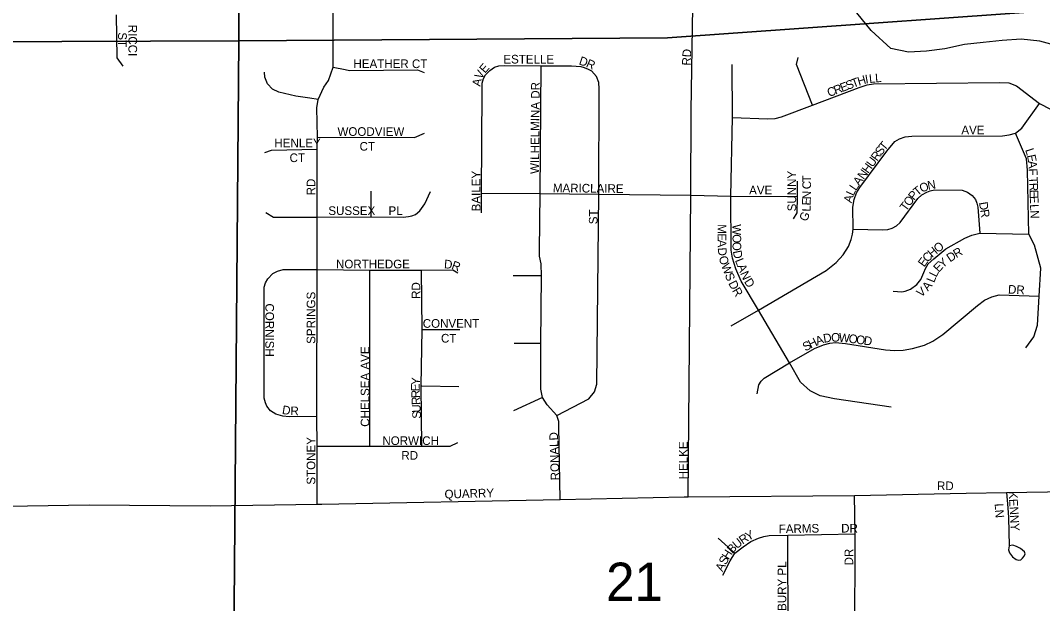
# Model space of a CAD drawing. Extents: x 8.5 to 81.5, y -1.2 to 22.4.
# Drawn here: x 50.981 to 52.1, y 18.242 to 18.88 of the extents above; entities that cross this region are included whole.
import ezdxf

# ---------------------------------------------------------------- set-up
doc = ezdxf.new("R2010")
doc.units = 0
for name, color, linetype in [('GM_X_City_Street', 7, 'Continuous'), ('GM_X_City_Street_Text', 7, 'Continuous'), ('GM_X_Minor_River', 7, 'Continuous'), ('GM_X_Section', 7, 'Continuous'), ('GM_X_Section_Text', 7, 'Continuous')]:
    doc.layers.add(name, color=color, linetype=linetype)

msp = doc.modelspace()

# ---------------------------------------------------------------- linework, layer by layer
at = {"layer": 'GM_X_City_Street'}
for points in [[(51.7122, 18.359), (51.715, 18.6889), (51.7156, 18.7812), (51.7174, 18.8951), (51.7191, 18.9313), (51.7226, 19.0378), (51.7258, 19.1233)], [(51.3058, 18.3509), (51.3059, 18.4145), (51.3056, 18.4467), (51.3059, 18.6075), (51.3058, 18.6651), (51.3059, 18.7393), (51.3062, 18.7524), (51.3056, 18.7847), (51.3071, 18.7938), (51.3132, 18.8072), (51.3182, 18.8144), (51.3234, 18.8291), (51.3232, 18.8883)], [(51.0858, 18.8862), (51.0865, 18.8393), (51.0929, 18.8302)], [(51.8486, 18.7875), (51.831, 18.832), (51.8326, 18.8398)], [(51.3071, 18.7938), (51.2978, 18.795), (51.2823, 18.7974), (51.2638, 18.8018), (51.2569, 18.805), (51.2514, 18.8109), (51.2485, 18.8182), (51.2482, 18.8235)], [(51.3234, 18.8291), (51.3364, 18.8264), (51.3414, 18.8254), (51.4157, 18.8262), (51.4231, 18.8232)], [(51.4857, 18.6698), (51.4857, 18.6912), (51.4865, 18.8033), (51.4865, 18.8116), (51.4881, 18.8166), (51.4904, 18.8207), (51.4948, 18.8255), (51.5, 18.8291)], [(51.5, 18.8291), (51.505, 18.8306), (51.5107, 18.831), (51.5513, 18.8307), (51.5846, 18.8306), (51.5947, 18.8299), (51.5983, 18.8288), (51.6026, 18.827), (51.6063, 18.825)], [(51.5683, 18.448), (51.5577, 18.4597), (51.5528, 18.4675), (51.5508, 18.4767), (51.5509, 18.5265), (51.5517, 18.6008), (51.5513, 18.6138), (51.5493, 18.6223), (51.5493, 18.6286), (51.55, 18.691), (51.5513, 18.8307)], [(51.5721, 18.3561), (51.5705, 18.436), (51.5705, 18.4413), (51.5683, 18.448), (51.6035, 18.4661), (51.6098, 18.4739), (51.6122, 18.4823), (51.6144, 18.6901), (51.6149, 18.8055), (51.6145, 18.8123), (51.6118, 18.8189), (51.6063, 18.825)], [(51.9346, 18.4569), (51.8726, 18.4663), (51.857, 18.4695), (51.8458, 18.4749), (51.8354, 18.4843), (51.8233, 18.5054), (51.7893, 18.5632), (51.7703, 18.5948), (51.7645, 18.6085), (51.7607, 18.6199), (51.7593, 18.6289), (51.7591, 18.6881), (51.7609, 18.7739), (51.7606, 18.8319)], [(51.7609, 18.7739), (51.799, 18.7725), (51.8074, 18.773), (51.8146, 18.7746), (51.8486, 18.7875), (51.8997, 18.8069), (51.9083, 18.8096), (51.9153, 18.8107), (52.0531, 18.8123), (52.0634, 18.8118), (52.072, 18.8085), (52.0969, 18.7893), (52.1092, 18.7833), (52.1164, 18.7805), (52.1264, 18.779), (52.1424, 18.7778), (52.2174, 18.7786)], [(51.7595, 18.5461), (51.7893, 18.5632), (51.8634, 18.6067), (51.8742, 18.6152), (51.8819, 18.6237), (51.8877, 18.6327), (51.8908, 18.6406), (51.8923, 18.6462), (51.8931, 18.6518), (51.8927, 18.6757), (51.8939, 18.6841), (51.8968, 18.6915), (51.9003, 18.6974), (51.9299, 18.7371), (51.9387, 18.7479), (51.9437, 18.7507), (51.9499, 18.753), (51.9573, 18.7535), (52.0565, 18.754), (52.0639, 18.7551), (52.0707, 18.7569), (52.0776, 18.7624), (52.0969, 18.7893)], [(51.3062, 18.7524), (51.4125, 18.7522), (51.4235, 18.7569)], [(52.0822, 18.5221), (52.091, 18.5341), (52.0948, 18.5467), (52.0968, 18.5783), (52.0986, 18.6091), (52.0917, 18.6343), (52.0854, 18.6463), (52.0841, 18.7162), (52.0828, 18.7288), (52.0707, 18.7569)], [(51.2486, 18.7356), (51.2557, 18.7384), (51.3059, 18.7393)], [(51.8276, 18.6632), (51.8315, 18.6698), (51.8319, 18.6876), (51.8321, 18.7044)], [(51.3058, 18.6651), (51.3651, 18.6653), (51.4, 18.6651), (51.4059, 18.6656), (51.4095, 18.6663), (51.4135, 18.6679), (51.4182, 18.6719), (51.4236, 18.6795), (51.43, 18.6929)], [(51.3651, 18.6653), (51.365, 18.6934)], [(51.4857, 18.6912), (51.55, 18.691), (51.6144, 18.6901), (51.715, 18.6889), (51.7591, 18.6881), (51.8319, 18.6876)], [(51.8931, 18.6518), (51.925, 18.651), (51.9309, 18.6515), (51.9358, 18.6529), (51.9405, 18.6553), (51.9444, 18.6591), (51.9639, 18.6855), (51.9681, 18.6895), (51.9736, 18.6924), (51.9773, 18.6939), (51.982, 18.6948), (52.0124, 18.6945), (52.0181, 18.6924), (52.0233, 18.6887), (52.0269, 18.6842), (52.0285, 18.6801), (52.0296, 18.676), (52.0319, 18.6473)], [(51.2496, 18.6699), (51.2581, 18.665), (51.3058, 18.6651)], [(51.9368, 18.5838), (51.9463, 18.5834), (51.9498, 18.584), (51.9557, 18.5863), (51.9626, 18.5912), (51.967, 18.5966), (51.9704, 18.6042), (51.9721, 18.6088), (51.9752, 18.6137), (51.9813, 18.6195), (51.9946, 18.6302), (52.0154, 18.6418), (52.0231, 18.6454), (52.0319, 18.6473), (52.0854, 18.6463)], [(51.3056, 18.4467), (51.275, 18.4464), (51.2681, 18.447), (51.2605, 18.4494), (51.2546, 18.4531), (51.2508, 18.458), (51.2491, 18.4618), (51.2479, 18.4667), (51.2477, 18.4714), (51.2477, 18.5883), (51.2493, 18.5932), (51.2518, 18.5974), (51.2573, 18.6033), (51.2624, 18.606), (51.2686, 18.6075)], [(51.2686, 18.6075), (51.3059, 18.6075), (51.3635, 18.607), (51.42, 18.6068), (51.4543, 18.6072), (51.4601, 18.6041)], [(51.3637, 18.4142), (51.3635, 18.607)], [(51.4206, 18.4142), (51.4198, 18.4805), (51.4208, 18.5421), (51.42, 18.6068)], [(51.5517, 18.6008), (51.5204, 18.6009)], [(51.7879, 18.4715), (51.7898, 18.4814), (51.7921, 18.4853), (51.7956, 18.4887), (51.8233, 18.5054), (51.8505, 18.5211), (51.8604, 18.5253), (51.8673, 18.5272), (51.8737, 18.5276), (51.8845, 18.5265), (51.9283, 18.5196), (51.9386, 18.5189), (51.9478, 18.5195), (51.958, 18.5211), (51.9712, 18.525), (51.9801, 18.5291), (51.9913, 18.5364), (52.029, 18.5681), (52.0367, 18.5741), (52.045, 18.5779), (52.053, 18.5798), (52.0968, 18.5783)], [(51.4208, 18.5421), (51.462, 18.5421)], [(51.5509, 18.5265), (51.5218, 18.5265)], [(51.4198, 18.4805), (51.4206, 18.4805), (51.461, 18.4797)], [(51.5528, 18.4675), (51.5208, 18.453)], [(51.3059, 18.4145), (51.3637, 18.4142), (51.4206, 18.4142), (51.4514, 18.4142), (51.46, 18.4182)], [(51.7078, 18.3589), (51.7122, 18.359), (51.8946, 18.3605), (52.0166, 18.3628), (52.0609, 18.3636), (52.1282, 18.3647), (52.2138, 18.3662)], [(52.0609, 18.3636), (52.0624, 18.3467), (52.0631, 18.3363), (52.064, 18.3054), (52.0631, 18.3009), (52.0642, 18.2975), (52.0674, 18.2932), (52.0716, 18.2903), (52.0741, 18.2896), (52.0766, 18.2901), (52.0786, 18.2917), (52.0804, 18.2941), (52.0813, 18.2966), (52.0806, 18.2988), (52.0764, 18.3022), (52.0719, 18.3047), (52.0678, 18.3058), (52.064, 18.3054)], [(50.8944, 18.3484), (50.9434, 18.3484), (51.0561, 18.3501), (51.1886, 18.349), (51.3058, 18.3509), (51.3111, 18.351)], [(51.3111, 18.351), (51.5721, 18.3561), (51.7078, 18.3589)], [(51.8743, 18.1572), (51.8844, 18.1707), (51.8897, 18.1812), (51.894, 18.1934), (51.8949, 18.2009), (51.895, 18.3183), (51.8946, 18.3605)], [(51.7502, 18.2733), (51.7581, 18.2889), (51.7635, 18.2974), (51.7723, 18.3043), (51.7807, 18.3101), (51.7892, 18.3135), (51.795, 18.3156), (51.801, 18.3164), (51.8215, 18.3169), (51.895, 18.3183)], [(51.8218, 18.2082), (51.8215, 18.3169)], [(51.7635, 18.2974), (51.745, 18.3136)]]:
    msp.add_lwpolyline(points, dxfattribs=at)
at = {"layer": 'GM_X_Minor_River'}
msp.add_lwpolyline([(52.1177, 18.8519), (52.0975, 18.8576), (52.077, 18.8598), (52.0561, 18.8583), (52.0352, 18.856), (52.015, 18.8538), (51.9933, 18.8492), (51.9732, 18.8466), (51.9534, 18.8454), (51.9344, 18.8496), (51.9127, 18.8694), (51.8971, 18.8887), (51.8842, 18.9085), (51.8785, 18.9305), (51.8758, 18.9514), (51.8682, 18.9708), (51.8541, 18.9898), (51.8401, 19.0114), (51.8279, 19.0316), (51.8085, 19.0278), (51.7948, 19.0197)], dxfattribs=at)
at = {"layer": 'GM_X_Section'}
for points in [[(51.2391, 19.8686), (51.2184, 19.3702), (51.2202, 18.8578), (50.2509, 18.8543), (50.2547, 19.342), (50.2812, 19.8687)], [(52.284, 19.8673), (52.2219, 19.2023), (52.2136, 18.8983), (51.6895, 18.8611), (51.2202, 18.8578), (51.2184, 19.3702), (51.2391, 19.8686)], [(52.2136, 18.8983), (52.2149, 17.8371), (51.2117, 17.8427), (51.2202, 18.8578), (51.6895, 18.8611)], [(50.2509, 18.8543), (51.2202, 18.8578), (51.2117, 17.8427), (50.2502, 17.8478)]]:
    msp.add_lwpolyline(points, close=True, dxfattribs=at)

# ---------------------------------------------------------------- texts
at = {"layer": 'GM_X_City_Street_Text'}
for s, rotation, p in [('ST', 270, (51.0878, 18.8672)), ('RICCI', 270, (51.0991, 18.8755)), ('RD', 86.989, (51.7148, 18.8306)), ('HEATHER CT', 0, (51.3456, 18.8281)), ('E', 49.4491, (51.4897, 18.8218)), ('ESTELLE', 0, (51.5098, 18.8331)), ('D', 341.7932, (51.5919, 18.8322)), ('R', 336.0967, (51.5996, 18.8297)), ('V', 60.678, (51.4859, 18.815)), ('I', 9.5773, (51.9068, 18.8111)), ('L', 5.5828, (51.9108, 18.8117)), ('L', 4.0194, (51.9173, 18.8124)), ('A', 79.5173, (51.4846, 18.8075)), ('WILHELMINA DR', 89.4932, (51.5488, 18.7122)), ('R', 20.9398, (51.8736, 18.799)), ('E', 20.9477, (51.8807, 18.8017)), ('S', 20.9493, (51.8869, 18.8041)), ('T', 20.6296, (51.8931, 18.8064)), ('H', 16.672, (51.8992, 18.8087)), ('C', 20.9398, (51.8666, 18.7963)), ('AVE', 0, (52.0115, 18.7556)), ('WOODVIEW', 0, (51.3281, 18.7539)), ('HENLEY', 0, (51.259, 18.7414)), ('CT', 0, (51.3523, 18.7377)), ('S', 53.4142, (51.9236, 18.7317)), ('T', 50.3204, (51.9275, 18.7369)), ('CT', 0, (51.2756, 18.7252)), ('R', 53.96, (51.9192, 18.7256)), ('L', 287.8756, (52.0812, 18.7386)), ('E', 281.5744, (52.0832, 18.7325)), ('H', 53.9768, (51.9094, 18.7121)), ('U', 53.9389, (51.9143, 18.7189)), ('A', 275.2732, (52.0845, 18.7263)), ('BAILEY', 90, (51.4847, 18.6713)), ('SUNNY', 90, (51.8305, 18.6713)), ('T', 89.9707, (51.8468, 18.703)), ('N', 53.9389, (51.9045, 18.7054)), ('F', 272.1226, (52.0853, 18.7181)), ('T', 272.1226, (52.0856, 18.709)), ('RD', 90, (51.3038, 18.6888)), ('MARICLAIRE', 359.3342, (51.564, 18.6923)), ('AVE', 0, (51.779, 18.6898)), ('C', 89.7445, (51.8468, 18.6955)), ('L', 55.5674, (51.8959, 18.6932)), ('A', 53.9694, (51.8996, 18.6987)), ('T', 39.893, (51.9636, 18.6875)), ('O', 24.8545, (51.9681, 18.6915)), ('N', 10.1055, (51.9751, 18.6948)), ('R', 272.1226, (52.0859, 18.7023)), ('N', 89.0919, (51.8466, 18.6845)), ('A', 75.3276, (51.8913, 18.6799)), ('L', 65.4633, (51.8933, 18.6875)), ('O', 53.3616, (51.9548, 18.6761)), ('P', 51.2719, (51.9597, 18.6827)), ('E', 272.1226, (52.0861, 18.6948)), ('E', 272.1226, (52.0864, 18.6881)), ('SUSSEX', 0, (51.3181, 18.6673)), ('PL', 0, (51.384, 18.6673)), ('L', 88.6244, (51.8462, 18.671)), ('E', 87.7039, (51.8463, 18.6776)), ('T', 53.3541, (51.9508, 18.6707)), ('D', 279.642, (52.0307, 18.6809)), ('L', 272.1226, (52.0867, 18.679)), ('ST', 90, (51.613, 18.6572)), ('G', 66.8387, (51.8421, 18.6595)), ('R', 278.3087, (52.0321, 18.6728)), ('N', 272.1226, (52.087, 18.6723)), ('M', 270, (51.7444, 18.6572)), ('W', 270.269, (51.7607, 18.6572)), ('E', 270.1204, (51.7444, 18.6471)), ('O', 270.2623, (51.7608, 18.6463)), ('A', 270.8829, (51.7445, 18.6403)), ('D', 274.7569, (51.7446, 18.6313)), ('O', 270.5445, (51.7608, 18.6379)), ('H', 40.4353, (51.9795, 18.6201)), ('O', 38.885, (51.9858, 18.6254)), ('R', 30.5222, (52.006, 18.6199)), ('O', 285.073, (51.7456, 18.6212)), ('D', 281.735, (51.7611, 18.6276)), ('L', 291.6527, (51.7633, 18.6177)), ('E', 54.294, (51.9708, 18.6097)), ('C', 45.687, (51.9744, 18.6149)), ('Y', 39.8615, (51.991, 18.6086)), ('D', 34.1022, (51.9992, 18.6153)), ('NORTHEDGE', 0, (51.3265, 18.6089)), ('D', 356.2819, (51.4446, 18.609)), ('R', 340.0978, (51.4523, 18.6086)), ('W', 291.3198, (51.7482, 18.6121)), ('A', 291.9872, (51.7658, 18.6115)), ('E', 46.2172, (51.9866, 18.604)), ('S', 292.0327, (51.7521, 18.6018)), ('N', 293.5991, (51.769, 18.6035)), ('D', 302.4871, (51.7731, 18.5944)), ('L', 68.0259, (51.9816, 18.5926)), ('L', 63.0317, (51.984, 18.5986)), ('RD', 90, (51.4188, 18.5755)), ('D', 296.8823, (51.756, 18.5926)), ('R', 300.3998, (51.7601, 18.5846)), ('V', 40.8858, (51.9673, 18.5767)), ('A', 51.2494, (51.9749, 18.5835)), ('DR', 356.9884, (52.0624, 18.5814)), ('SPRINGS', 90, (51.3038, 18.5263)), ('CORNISH', 270, (51.2491, 18.5705)), ('CONVENT', 0, (51.4215, 18.5439)), ('CT', 0, (51.4415, 18.5277)), ('H', 25.7048, (51.8464, 18.521)), ('A', 20.8963, (51.8537, 18.5245)), ('D', 9.8611, (51.861, 18.5274)), ('O', 359.694, (51.8688, 18.5287)), ('W', 354.696, (51.8769, 18.5287)), ('O', 352.5686, (51.8876, 18.5277)), ('O', 352.3057, (51.8958, 18.5266)), ('D', 352.284, (51.9041, 18.5255)), ('CHELSEA AVE', 90, (51.363, 18.4355)), ('S', 28.0677, (51.8406, 18.5179)), ('Y', 86.3473, (51.4182, 18.4809)), ('E', 90.9289, (51.4183, 18.4745)), ('R', 92.5993, (51.4186, 18.4671)), ('R', 92.6298, (51.419, 18.4596)), ('D', 350.8036, (51.2669, 18.4497)), ('R', 358.8153, (51.2765, 18.4483)), ('U', 92.6083, (51.4194, 18.4512)), ('S', 92.5964, (51.4197, 18.4446)), ('RONALD', 91.9739, (51.5713, 18.3771)), ('STONEY', 90, (51.3038, 18.3722)), ('NORWICH', 0, (51.3773, 18.4156)), ('HELKE', 90, (51.7115, 18.378)), ('RD', 0, (51.3981, 18.3995)), ('RD', 0, (51.9848, 18.3662)), ('QUARRY', 1.6594, (51.4455, 18.357)), ('KENNY', 273.5046, (52.0632, 18.3648)), ('L', 273.0616, (52.048, 18.3514)), ('N', 274.7084, (52.0483, 18.3445)), ('FARMS', 1.0065, (51.8115, 18.319)), ('DR', 0, (51.8798, 18.3198)), ('R', 34.2559, (51.7719, 18.3065)), ('Y', 26.3109, (51.7778, 18.3105)), ('B', 46.3737, (51.7606, 18.2962)), ('U', 38.7588, (51.7655, 18.3014)), ('H', 58.414, (51.7565, 18.2895)), ('DR', 90, (51.893, 18.2838)), ('A', 63.1515, (51.7499, 18.2763)), ('S', 62.9463, (51.7536, 18.2837)), ('ASHBURY PL', 90, (51.8197, 18.208))]:
    msp.add_text(s, height=0.00947, rotation=rotation, dxfattribs=at).set_placement(p)
at = {"layer": 'GM_X_Section_Text'}
msp.add_text('21', height=0.04186, rotation=0, dxfattribs=at).set_placement((51.6223, 18.245))

doc.saveas('drawing.dxf')
